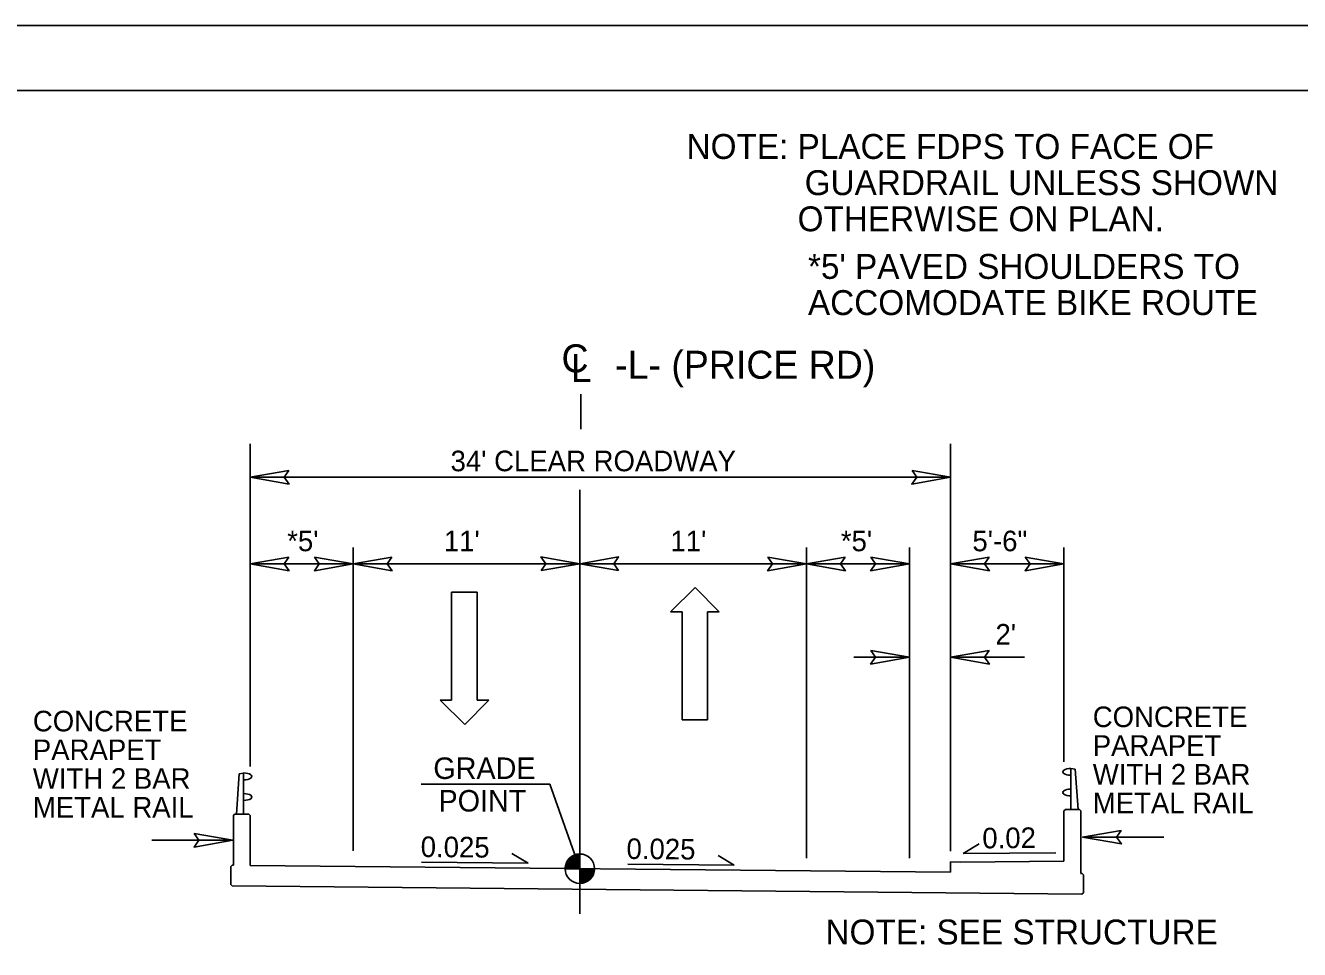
# Model space of a CAD drawing. Extents: x 1184121 to 1184397, y 1246506 to 1246661.
# Drawn here: x 1184280.8 to 1184342.6, y 1246615.6 to 1246660.5 of the extents above; entities that cross this region are included whole.
import ezdxf

# ---------------------------------------------------------------- set-up
doc = ezdxf.new("R2010")
doc.units = 0
for name, color, linetype in [('Prop Shade Light', 7, 'Continuous'), ('Sheet Data Field CELL', 7, 'Continuous'), ('Sheet Plan CELL', 7, 'Continuous'), ('Sheet Plot Border Outside CELL', 7, 'Continuous'), ('Typical Text Label CELL', 7, 'Continuous'), ('z - Construction', 7, 'Continuous')]:
    doc.layers.add(name, color=color, linetype=linetype)

msp = doc.modelspace()

# ---------------------------------------------------------------- linework, layer by layer
at = {"layer": 'Prop Shade Light'}
msp.add_line((1184331.991, 1246622.383), (1184331.991, 1246619.945), dxfattribs=at)
at = {"layer": 'Sheet Data Field CELL'}
for p, q in [((1184307.721, 1246640.924), (1184307.721, 1246642.622)), ((1184291.672, 1246624.547), (1184291.672, 1246640.209)), ((1184325.672, 1246620.433), (1184325.672, 1246640.209)), ((1184325.672, 1246638.588), (1184291.672, 1246638.588)), ((1184307.672, 1246617.38), (1184307.672, 1246637.976)), ((1184296.672, 1246620.443), (1184296.672, 1246635.182)), ((1184318.672, 1246620.079), (1184318.672, 1246635.182)), ((1184323.672, 1246620.079), (1184323.672, 1246635.182)), ((1184331.172, 1246624.765), (1184331.172, 1246635.182)), ((1184291.672, 1246634.382), (1184296.672, 1246634.382)), ((1184307.672, 1246634.382), (1184296.672, 1246634.382)), ((1184307.672, 1246634.382), (1184318.672, 1246634.382)), ((1184318.677, 1246634.382), (1184323.672, 1246634.382)), ((1184325.672, 1246634.381), (1184331.172, 1246634.381)), ((1184301.449, 1246627.763), (1184301.449, 1246633.013)), ((1184301.449, 1246633.013), (1184302.687, 1246633.013)), ((1184302.687, 1246633.013), (1184302.687, 1246627.763)), ((1184313.274, 1246633.23), (1184312.074, 1246632.049)), ((1184314.436, 1246632.049), (1184313.274, 1246633.23)), ((1184312.074, 1246632.049), (1184312.636, 1246632.049)), ((1184312.636, 1246632.049), (1184312.636, 1246626.799)), ((1184313.874, 1246626.799), (1184313.874, 1246632.049)), ((1184313.874, 1246632.049), (1184314.436, 1246632.049)), ((1184320.971, 1246629.849), (1184323.672, 1246629.849)), ((1184325.672, 1246629.849), (1184329.256, 1246629.849)), ((1184302.087, 1246626.581), (1184300.887, 1246627.763)), ((1184300.887, 1246627.763), (1184301.449, 1246627.763)), ((1184303.249, 1246627.763), (1184302.087, 1246626.581)), ((1184302.687, 1246627.763), (1184303.249, 1246627.763)), ((1184312.636, 1246626.799), (1184313.874, 1246626.799)), ((1184291.353, 1246624.223), (1184291.142, 1246624.181)), ((1184291.353, 1246622.223), (1184291.353, 1246624.223)), ((1184291.353, 1246624.223), (1184291.353, 1246623.89)), ((1184331.512, 1246622.445), (1184331.512, 1246624.445)), ((1184331.512, 1246624.445), (1184331.723, 1246624.403)), ((1184331.512, 1246624.445), (1184331.512, 1246624.112)), ((1184331.723, 1246624.403), (1184331.866, 1246622.445)), ((1184291.142, 1246624.181), (1184290.999, 1246622.223)), ((1184299.978, 1246623.684), (1184305.639, 1246623.684)), ((1184299.978, 1246623.684), (1184306.223, 1246623.684)), ((1184307.672, 1246619.572), (1184306.223, 1246623.684)), ((1184291.353, 1246623.223), (1184291.353, 1246622.89)), ((1184331.512, 1246623.445), (1184331.512, 1246623.112)), ((1184331.241, 1246622.445), (1184331.172, 1246622.383)), ((1184331.172, 1246619.945), (1184331.172, 1246622.383)), ((1184331.928, 1246622.445), (1184331.241, 1246622.445)), ((1184331.512, 1246622.445), (1184331.866, 1246622.445)), ((1184331.928, 1246622.445), (1184331.991, 1246622.383)), ((1184331.991, 1246619.346), (1184331.991, 1246622.383)), ((1184290.915, 1246622.223), (1184290.853, 1246622.161)), ((1184290.853, 1246619.748), (1184290.853, 1246622.161)), ((1184290.915, 1246622.223), (1184291.603, 1246622.223)), ((1184291.353, 1246622.223), (1184290.999, 1246622.223)), ((1184291.603, 1246622.223), (1184291.672, 1246622.161)), ((1184291.672, 1246619.723), (1184291.672, 1246622.161)), ((1184332.075, 1246621.114), (1184336.027, 1246621.114)), ((1184290.829, 1246620.963), (1184286.889, 1246620.963)), ((1184326.273, 1246620.311), (1184327.061, 1246620.776)), ((1184305.157, 1246619.846), (1184299.994, 1246619.89)), ((1184305.157, 1246619.846), (1184304.37, 1246620.311)), ((1184307.672, 1246619.572), (1184307.672, 1246620.288)), ((1184315.169, 1246619.752), (1184314.381, 1246620.217)), ((1184325.672, 1246619.403), (1184325.672, 1246619.903)), ((1184325.672, 1246619.903), (1184326.172, 1246619.898)), ((1184326.172, 1246619.898), (1184331.172, 1246619.945)), ((1184326.273, 1246620.311), (1184330.78, 1246620.348)), ((1184290.79, 1246619.747), (1184290.728, 1246619.684)), ((1184290.728, 1246618.809), (1184290.728, 1246619.684)), ((1184290.79, 1246619.747), (1184290.853, 1246619.748)), ((1184325.672, 1246619.403), (1184291.672, 1246619.723)), ((1184306.956, 1246619.572), (1184307.672, 1246619.572)), ((1184307.673, 1246618.856), (1184307.672, 1246619.572)), ((1184308.388, 1246619.572), (1184307.672, 1246619.572)), ((1184307.672, 1246619.572), (1184307.673, 1246618.856)), ((1184315.169, 1246619.752), (1184310.005, 1246619.796)), ((1184332.053, 1246619.345), (1184331.991, 1246619.346)), ((1184332.053, 1246619.345), (1184332.116, 1246619.282)), ((1184332.116, 1246618.407), (1184332.116, 1246619.282)), ((1184290.728, 1246618.809), (1184290.8, 1246618.738)), ((1184332.044, 1246618.336), (1184290.8, 1246618.738)), ((1184332.116, 1246618.407), (1184332.044, 1246618.336))]:
    msp.add_line(p, q, dxfattribs=at)
for points in [[(1184293.546, 1246638.911), (1184291.672, 1246638.588), (1184293.557, 1246638.254), (1184293.317, 1246638.588)], [(1184323.797, 1246638.911), (1184325.672, 1246638.588), (1184323.787, 1246638.254), (1184324.026, 1246638.588)], [(1184293.546, 1246634.704), (1184291.672, 1246634.382), (1184293.557, 1246634.048), (1184293.317, 1246634.382)], [(1184294.797, 1246634.704), (1184296.672, 1246634.382), (1184294.787, 1246634.048), (1184295.026, 1246634.382)], [(1184298.546, 1246634.704), (1184296.672, 1246634.382), (1184298.557, 1246634.048), (1184298.317, 1246634.382)], [(1184305.797, 1246634.059), (1184307.672, 1246634.382), (1184305.787, 1246634.715), (1184306.026, 1246634.382)], [(1184309.546, 1246634.059), (1184307.672, 1246634.382), (1184309.557, 1246634.715), (1184309.317, 1246634.382)], [(1184316.797, 1246634.704), (1184318.672, 1246634.382), (1184316.787, 1246634.048), (1184317.026, 1246634.382)], [(1184320.552, 1246634.705), (1184318.677, 1246634.382), (1184320.562, 1246634.048), (1184320.323, 1246634.382)], [(1184321.797, 1246634.704), (1184323.672, 1246634.382), (1184321.787, 1246634.048), (1184322.026, 1246634.382)], [(1184327.546, 1246634.704), (1184325.672, 1246634.381), (1184327.557, 1246634.048), (1184327.317, 1246634.381)], [(1184329.297, 1246634.704), (1184331.172, 1246634.381), (1184329.287, 1246634.048), (1184329.526, 1246634.381)], [(1184321.797, 1246630.172), (1184323.672, 1246629.849), (1184321.787, 1246629.516), (1184322.026, 1246629.849)], [(1184327.546, 1246630.172), (1184325.672, 1246629.849), (1184327.557, 1246629.515), (1184327.317, 1246629.849)], [(1184288.955, 1246621.285), (1184290.829, 1246620.963), (1184288.944, 1246620.629), (1184289.184, 1246620.963)], [(1184333.95, 1246621.437), (1184332.075, 1246621.114), (1184333.96, 1246620.781), (1184333.721, 1246621.114)]]:
    msp.add_lwpolyline(points, close=True, dxfattribs=at)
for points in [[(1184307.021, 1246619.87), (1184307.021, 1246619.572)], [(1184307.035, 1246619.9), (1184307.035, 1246619.572)], [(1184307.049, 1246619.926), (1184307.049, 1246619.572)], [(1184307.064, 1246619.95), (1184307.064, 1246619.572)], [(1184307.078, 1246619.972), (1184307.078, 1246619.572)], [(1184307.092, 1246619.993), (1184307.092, 1246619.572)], [(1184307.107, 1246620.012), (1184307.107, 1246619.572)], [(1184307.121, 1246620.029), (1184307.121, 1246619.572)], [(1184307.135, 1246620.047), (1184307.135, 1246619.572)], [(1184307.15, 1246620.063), (1184307.15, 1246619.572)], [(1184307.164, 1246620.077), (1184307.164, 1246619.572)], [(1184307.178, 1246620.091), (1184307.178, 1246619.572)], [(1184307.193, 1246620.104), (1184307.193, 1246619.572)], [(1184307.207, 1246620.117), (1184307.207, 1246619.572)], [(1184307.221, 1246620.129), (1184307.221, 1246619.572)], [(1184307.236, 1246620.14), (1184307.236, 1246619.572)], [(1184307.25, 1246620.15), (1184307.25, 1246619.572)], [(1184307.264, 1246620.161), (1184307.264, 1246619.572)], [(1184307.279, 1246620.171), (1184307.279, 1246619.572)], [(1184307.293, 1246620.18), (1184307.293, 1246619.572)], [(1184307.307, 1246620.188), (1184307.307, 1246619.572)], [(1184307.322, 1246620.196), (1184307.322, 1246619.572)], [(1184307.336, 1246620.204), (1184307.336, 1246619.572)], [(1184307.35, 1246620.212), (1184307.35, 1246619.572)], [(1184307.364, 1246620.218), (1184307.364, 1246619.572)], [(1184307.379, 1246620.225), (1184307.379, 1246619.572)], [(1184307.393, 1246620.231), (1184307.393, 1246619.572)], [(1184307.407, 1246620.238), (1184307.407, 1246619.572)], [(1184307.422, 1246620.244), (1184307.422, 1246619.572)], [(1184307.436, 1246620.249), (1184307.436, 1246619.572)], [(1184307.45, 1246620.253), (1184307.45, 1246619.572)], [(1184307.465, 1246620.258), (1184307.465, 1246619.572)], [(1184307.479, 1246620.261), (1184307.479, 1246619.572)], [(1184307.493, 1246620.266), (1184307.493, 1246619.572)], [(1184307.508, 1246620.269), (1184307.508, 1246619.572)], [(1184307.522, 1246620.273), (1184307.522, 1246619.572)], [(1184307.536, 1246620.276), (1184307.536, 1246619.572)], [(1184307.551, 1246620.279), (1184307.551, 1246619.572)], [(1184307.565, 1246620.281), (1184307.565, 1246619.572)], [(1184307.579, 1246620.282), (1184307.579, 1246619.572)], [(1184307.594, 1246620.284), (1184307.594, 1246619.572)], [(1184307.608, 1246620.285), (1184307.608, 1246619.572)], [(1184307.622, 1246620.287), (1184307.622, 1246619.572)], [(1184307.637, 1246620.287), (1184307.637, 1246619.572)], [(1184307.651, 1246620.288), (1184307.651, 1246619.572)], [(1184307.665, 1246620.288), (1184307.665, 1246620.288), (1184307.665, 1246619.572)], [(1184306.963, 1246619.674), (1184306.963, 1246619.572)], [(1184306.978, 1246619.747), (1184306.978, 1246619.572)], [(1184306.992, 1246619.797), (1184306.992, 1246619.572)], [(1184307.006, 1246619.837), (1184307.006, 1246619.572)], [(1184307.683, 1246619.572), (1184307.683, 1246618.856), (1184307.683, 1246618.856)], [(1184307.697, 1246619.572), (1184307.697, 1246618.856)], [(1184307.711, 1246619.572), (1184307.711, 1246618.858)], [(1184307.726, 1246619.572), (1184307.726, 1246618.858)], [(1184307.74, 1246619.572), (1184307.74, 1246618.859)], [(1184307.754, 1246619.572), (1184307.754, 1246618.861)], [(1184307.769, 1246619.572), (1184307.769, 1246618.863)], [(1184307.783, 1246619.572), (1184307.783, 1246618.866)], [(1184307.797, 1246619.572), (1184307.797, 1246618.867)], [(1184307.812, 1246619.572), (1184307.812, 1246618.871)], [(1184307.826, 1246619.572), (1184307.826, 1246618.874)], [(1184307.84, 1246619.572), (1184307.84, 1246618.877)], [(1184307.855, 1246619.572), (1184307.855, 1246618.88)], [(1184307.869, 1246619.572), (1184307.869, 1246618.885)], [(1184307.883, 1246619.572), (1184307.883, 1246618.888)], [(1184307.898, 1246619.572), (1184307.898, 1246618.893)], [(1184307.912, 1246619.572), (1184307.912, 1246618.898)], [(1184307.926, 1246619.572), (1184307.926, 1246618.902)], [(1184307.941, 1246619.572), (1184307.941, 1246618.909)], [(1184307.955, 1246619.572), (1184307.955, 1246618.915)], [(1184307.969, 1246619.572), (1184307.969, 1246618.921)], [(1184307.984, 1246619.572), (1184307.984, 1246618.928)], [(1184307.998, 1246619.572), (1184307.998, 1246618.934)], [(1184308.012, 1246619.572), (1184308.012, 1246618.942)], [(1184308.027, 1246619.572), (1184308.027, 1246618.95)], [(1184308.041, 1246619.572), (1184308.041, 1246618.958)], [(1184308.055, 1246619.572), (1184308.055, 1246618.968)], [(1184308.07, 1246619.572), (1184308.07, 1246618.977)], [(1184308.084, 1246619.572), (1184308.084, 1246618.987)], [(1184308.098, 1246619.572), (1184308.098, 1246618.996)], [(1184308.112, 1246619.572), (1184308.112, 1246619.007)], [(1184308.127, 1246619.572), (1184308.127, 1246619.019)], [(1184308.141, 1246619.572), (1184308.141, 1246619.031)], [(1184308.155, 1246619.572), (1184308.155, 1246619.044)], [(1184308.17, 1246619.572), (1184308.17, 1246619.057)], [(1184308.184, 1246619.572), (1184308.184, 1246619.071)], [(1184308.198, 1246619.572), (1184308.198, 1246619.087)], [(1184308.213, 1246619.572), (1184308.213, 1246619.103)], [(1184308.227, 1246619.572), (1184308.227, 1246619.12)], [(1184308.241, 1246619.572), (1184308.241, 1246619.138)], [(1184308.256, 1246619.572), (1184308.256, 1246619.157)], [(1184308.27, 1246619.572), (1184308.27, 1246619.178)], [(1184308.284, 1246619.572), (1184308.284, 1246619.2)], [(1184308.299, 1246619.572), (1184308.299, 1246619.225)], [(1184308.313, 1246619.572), (1184308.313, 1246619.252)], [(1184308.327, 1246619.572), (1184308.327, 1246619.283)], [(1184308.342, 1246619.572), (1184308.342, 1246619.316)], [(1184308.356, 1246619.572), (1184308.356, 1246619.359)], [(1184308.37, 1246619.572), (1184308.37, 1246619.41)], [(1184308.385, 1246619.572), (1184308.385, 1246619.494)]]:
    msp.add_lwpolyline(points, dxfattribs=at)
msp.add_circle((1184307.672, 1246619.573), 0.716, dxfattribs=at)
for start, end in [(90.00952, 180.00952), (270.00952, 0.00952)]:
    msp.add_arc((1184307.672, 1246619.573), 0.716, start, end, dxfattribs=at)
for centre, start_param, end_param in [((1184291.353, 1246624.057), 1.570796, 4.712389), ((1184331.512, 1246624.278), 4.712389, 7.853982), ((1184291.353, 1246623.057), 1.570796, 4.712389), ((1184331.512, 1246623.278), 4.712389, 7.853982)]:
    msp.add_ellipse(centre, major_axis=(-0.396, 0), ratio=0.421053, start_param=start_param, end_param=end_param, dxfattribs=at)
at = {"layer": 'Sheet Plan CELL'}
msp.add_line((1184358.423, 1246657.364), (1184126.184, 1246657.364), dxfattribs=at)
at = {"layer": 'Sheet Plot Border Outside CELL'}
msp.add_lwpolyline([(1184121.05, 1246660.53), (1184360.324, 1246660.53), (1184360.324, 1246505.708), (1184121.05, 1246505.708)], close=True, dxfattribs=at)
at = {"layer": 'z - Construction'}
msp.add_line((1184360.324, 1246660.53), (1184121.05, 1246660.53), dxfattribs=at)

# ---------------------------------------------------------------- texts
at = {"layer": 'Sheet Data Field CELL'}
for s, height, p in [('C', 1.36, (1184306.783, 1246643.682)), ('-L- (PRICE RD)', 1.36, (1184309.388, 1246643.372)), ("34' CLEAR ROADWAY", 1, (1184301.397, 1246638.879)), ("11'", 1, (1184301.072, 1246634.994)), ("11'", 1, (1184312.072, 1246634.994)), ('GRADE', 1.044, (1184300.56, 1246623.934)), ('POINT', 1.044, (1184300.812, 1246622.352))]:
    msp.add_text(s, height=height, dxfattribs=at).set_placement(p)
for s, height, rotation, p in [('L', 1.361, 359.9469, (1184307.236, 1246643.217)), ("*5'", 1, 359.99977, (1184293.468, 1246634.994)), ("*5'", 1, 0.00023, (1184320.343, 1246634.994)), ('5\'-6"', 1, 0.00023, (1184326.729, 1246634.993)), ("2'", 1, 0.00023, (1184327.849, 1246630.461)), ('CONCRETE', 1, 0.00023, (1184332.572, 1246626.452)), ('CONCRETE', 1, 0.00023, (1184281.122, 1246626.245)), ('PARAPET ', 1, 0.00023, (1184332.572, 1246625.057)), ('PARAPET ', 1, 0.00023, (1184281.122, 1246624.85)), ('WITH 2 BAR', 1, 0.00023, (1184281.122, 1246623.455)), ('WITH 2 BAR', 1, 0.00023, (1184332.572, 1246623.662)), ('METAL RAIL', 1, 0.00023, (1184281.122, 1246622.06)), ('METAL RAIL', 1, 0.00023, (1184332.572, 1246622.267)), ('0.025', 1, 359.45976, (1184299.944, 1246620.144)), ('0.02', 1, 0.54024, (1184327.215, 1246620.559)), ('0.025', 1, 359.45976, (1184309.936, 1246620.049))]:
    msp.add_text(s, height=height, rotation=rotation, dxfattribs=at).set_placement(p)
at = {"layer": 'Typical Text Label CELL'}
for s, p in [('NOTE: PLACE FDPS TO FACE OF ', (1184312.853, 1246654.049)), ('  GUARDRAIL UNLESS SHOWN', (1184317.688, 1246652.291)), ('            OTHERWISE ON PLAN.', (1184312.853, 1246650.534)), ("*5' PAVED SHOULDERS TO", (1184318.747, 1246648.223)), ('ACCOMODATE BIKE ROUTE', (1184318.747, 1246646.466)), ('  NOTE: SEE STRUCTURE', (1184318.699, 1246615.897))]:
    msp.add_text(s, height=1.20892, dxfattribs=at).set_placement(p)

doc.saveas('drawing.dxf')
